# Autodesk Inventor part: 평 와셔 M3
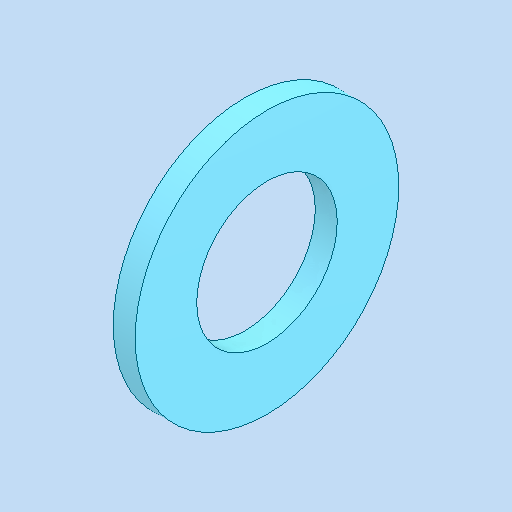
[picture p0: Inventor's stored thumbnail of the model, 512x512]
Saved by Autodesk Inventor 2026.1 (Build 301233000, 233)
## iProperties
Created: 2025-09
Part Number: 평 와셔 M3
Material: 강철, 연강
Description: 평면 와셔
Document SubType Name: Modeling
Designer: PC-30
Density: 7.85 g/cm^3
Appearance: 기본값
Author: jhkim
Sending System: Autodesk Inventor 2026
Preprocessor: ST-DEVELOPER v20.1
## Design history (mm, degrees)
feature "Solid1"
node "솔리드1"
